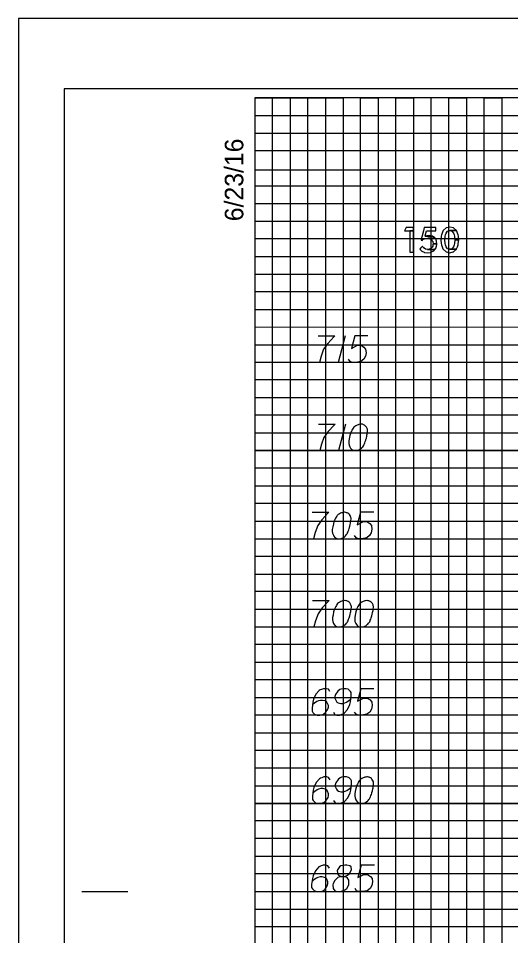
# Model space of a CAD drawing. Extents: x -13 to 323, y -5 to 1431.
# Drawn here: x -13.4 to 14.5, y 162.5 to 214.5 of the extents above; entities that cross this region are included whole.
import ezdxf

# ---------------------------------------------------------------- set-up
doc = ezdxf.new("R2010")
doc.units = 0
for name, color, linetype in [('Prop XS Elevation Labels', 7, 'Continuous'), ('Prop XS Offset Labels', 7, 'Continuous'), ('Sheet Cross Section CELL', 7, 'Continuous'), ('Sheet Cross Section Grid Major CELL', 7, 'Continuous'), ('Sheet Cross Section Grid Middle CELL', 7, 'Continuous'), ('Sheet Cross Section Grid Minor 1 CELL', 7, 'Continuous'), ('Sheet Cross Section Grid Minor 2 CELL', 7, 'Continuous'), ('Sheet Cutting Line CELL', 7, 'Continuous'), ('Sheet DOT Grid CELL', 7, 'Continuous'), ('Sheet Plot Border Inside CELL', 7, 'Continuous'), ('Sheet Plot Border Outside CELL', 7, 'Continuous')]:
    doc.layers.add(name, color=color, linetype=linetype)

msp = doc.modelspace()

# ---------------------------------------------------------------- linework, layer by layer
at = {"layer": 'Prop XS Elevation Labels'}
for p, q in [((5.124, 196.5), (4.723, 195)), ((5.142, 191.5), (4.74, 190))]:
    msp.add_line(p, q, dxfattribs=at)
for points in [[(3.589, 196.5), (4.533, 196.5), (4.474, 196.441), (4.132, 196.075), (3.896, 195.744), (3.754, 195.354), (3.659, 195)], [(6.411, 196.5), (5.667, 196.5), (5.478, 195.791), (5.821, 195.969), (6.022, 195.969), (6.187, 195.862), (6.282, 195.744), (6.305, 195.543), (6.27, 195.342), (6.175, 195.177), (6.01, 195.047), (5.726, 195), (5.514, 195), (5.408, 195.047), (5.313, 195.177)], [(3.606, 191.5), (4.551, 191.5), (4.492, 191.441), (4.149, 191.075), (3.913, 190.744), (3.772, 190.354), (3.677, 190)], [(6.039, 191.5), (6.016, 191.5), (5.945, 191.488), (5.898, 191.476), (5.862, 191.465), (5.803, 191.441), (5.732, 191.406), (5.673, 191.37), (5.614, 191.323), (5.579, 191.276), (5.543, 191.217), (5.508, 191.158), (5.472, 191.087), (5.449, 191.039), (5.425, 190.969), (5.39, 190.85), (5.354, 190.673), (5.331, 190.531), (5.331, 190.402), (5.343, 190.307), (5.39, 190.201), (5.425, 190.142), (5.484, 190.071), (5.555, 190.024), (5.591, 190.012), (5.661, 190), (5.72, 190), (5.815, 190.012), (5.898, 190.035), (5.957, 190.071), (6.039, 190.13), (6.075, 190.165), (6.122, 190.213), (6.157, 190.26), (6.181, 190.295), (6.205, 190.354), (6.217, 190.378), (6.24, 190.437), (6.264, 190.508), (6.287, 190.579), (6.299, 190.626), (6.311, 190.661), (6.323, 190.709), (6.347, 190.815), (6.358, 190.874), (6.37, 190.933), (6.382, 191.016), (6.394, 191.122), (6.394, 191.158), (6.382, 191.205), (6.37, 191.252), (6.335, 191.323), (6.299, 191.37), (6.264, 191.406), (6.217, 191.441), (6.169, 191.465), (6.134, 191.476), (6.098, 191.488), (6.039, 191.5)], [(3.258, 186.5), (4.203, 186.5), (4.144, 186.441), (3.801, 186.075), (3.565, 185.744), (3.423, 185.354), (3.329, 185)], [(5.1, 186.5), (5.077, 186.5), (5.006, 186.488), (4.959, 186.476), (4.923, 186.465), (4.864, 186.441), (4.793, 186.406), (4.734, 186.37), (4.675, 186.323), (4.64, 186.276), (4.604, 186.217), (4.569, 186.158), (4.534, 186.087), (4.51, 186.039), (4.486, 185.969), (4.451, 185.85), (4.415, 185.673), (4.392, 185.531), (4.392, 185.402), (4.404, 185.307), (4.451, 185.201), (4.486, 185.142), (4.545, 185.071), (4.616, 185.024), (4.652, 185.012), (4.723, 185), (4.781, 185), (4.876, 185.012), (4.959, 185.035), (5.018, 185.071), (5.1, 185.13), (5.136, 185.165), (5.183, 185.213), (5.219, 185.26), (5.242, 185.295), (5.266, 185.354), (5.278, 185.378), (5.301, 185.437), (5.325, 185.508), (5.349, 185.579), (5.36, 185.626), (5.372, 185.661), (5.384, 185.709), (5.408, 185.815), (5.419, 185.874), (5.431, 185.933), (5.443, 186.016), (5.455, 186.122), (5.455, 186.158), (5.443, 186.205), (5.431, 186.252), (5.396, 186.323), (5.36, 186.37), (5.325, 186.406), (5.278, 186.441), (5.23, 186.465), (5.195, 186.476), (5.16, 186.488), (5.1, 186.5)], [(6.742, 186.5), (5.998, 186.5), (5.809, 185.791), (6.152, 185.969), (6.352, 185.969), (6.518, 185.862), (6.612, 185.744), (6.636, 185.543), (6.6, 185.342), (6.506, 185.177), (6.341, 185.047), (6.057, 185), (5.845, 185), (5.738, 185.047), (5.644, 185.177)], [(3.276, 181.5), (4.22, 181.5), (4.161, 181.441), (3.819, 181.075), (3.583, 180.744), (3.441, 180.354), (3.346, 180)], [(5.118, 181.5), (5.094, 181.5), (5.024, 181.488), (4.977, 181.476), (4.941, 181.465), (4.882, 181.441), (4.811, 181.406), (4.752, 181.37), (4.693, 181.323), (4.658, 181.276), (4.622, 181.217), (4.587, 181.158), (4.551, 181.087), (4.528, 181.039), (4.504, 180.969), (4.469, 180.85), (4.433, 180.673), (4.409, 180.531), (4.409, 180.402), (4.421, 180.307), (4.469, 180.201), (4.504, 180.142), (4.563, 180.071), (4.634, 180.024), (4.669, 180.012), (4.74, 180), (4.799, 180), (4.894, 180.012), (4.977, 180.035), (5.036, 180.071), (5.118, 180.13), (5.154, 180.165), (5.201, 180.213), (5.236, 180.26), (5.26, 180.295), (5.283, 180.354), (5.295, 180.378), (5.319, 180.437), (5.342, 180.508), (5.366, 180.579), (5.378, 180.626), (5.39, 180.661), (5.402, 180.709), (5.425, 180.815), (5.437, 180.874), (5.449, 180.933), (5.461, 181.016), (5.473, 181.122), (5.473, 181.158), (5.461, 181.205), (5.449, 181.252), (5.413, 181.323), (5.378, 181.37), (5.342, 181.406), (5.295, 181.441), (5.248, 181.465), (5.213, 181.476), (5.177, 181.488), (5.118, 181.5)], [(6.37, 181.5), (6.346, 181.5), (6.276, 181.488), (6.228, 181.476), (6.193, 181.465), (6.134, 181.441), (6.063, 181.406), (6.004, 181.37), (5.945, 181.323), (5.909, 181.276), (5.874, 181.217), (5.838, 181.158), (5.803, 181.087), (5.779, 181.039), (5.756, 180.969), (5.721, 180.85), (5.685, 180.673), (5.661, 180.531), (5.661, 180.402), (5.673, 180.307), (5.721, 180.201), (5.756, 180.142), (5.815, 180.071), (5.886, 180.024), (5.921, 180.012), (5.992, 180), (6.051, 180), (6.146, 180.012), (6.228, 180.035), (6.287, 180.071), (6.37, 180.13), (6.406, 180.165), (6.453, 180.213), (6.488, 180.26), (6.512, 180.295), (6.535, 180.354), (6.547, 180.378), (6.571, 180.437), (6.594, 180.508), (6.618, 180.579), (6.63, 180.626), (6.642, 180.661), (6.653, 180.709), (6.677, 180.815), (6.689, 180.874), (6.701, 180.933), (6.713, 181.016), (6.724, 181.122), (6.724, 181.158), (6.713, 181.205), (6.701, 181.252), (6.665, 181.323), (6.63, 181.37), (6.594, 181.406), (6.547, 181.441), (6.5, 181.465), (6.464, 181.476), (6.429, 181.488), (6.37, 181.5)], [(4.262, 176.335), (4.168, 176.465), (4.061, 176.5), (3.896, 176.5), (3.778, 176.453), (3.707, 176.429), (3.648, 176.394), (3.459, 176.181), (3.329, 175.898), (3.294, 175.744), (3.246, 175.402), (3.246, 175.224), (3.294, 175.154), (3.388, 175.059), (3.423, 175.035), (3.542, 175), (3.695, 175), (3.813, 175.024), (3.896, 175.047), (4.014, 175.142), (4.132, 175.331), (4.168, 175.449), (4.168, 175.543), (4.109, 175.697), (4.061, 175.756), (3.979, 175.803), (3.837, 175.839), (3.73, 175.839), (3.601, 175.803), (3.518, 175.768), (3.376, 175.673), (3.305, 175.614), (3.27, 175.579)], [(4.451, 175.165), (4.545, 175.035), (4.652, 175), (4.817, 175), (4.935, 175.047), (5.006, 175.071), (5.065, 175.106), (5.254, 175.319), (5.384, 175.602), (5.419, 175.756), (5.467, 176.098), (5.467, 176.276), (5.419, 176.346), (5.325, 176.441), (5.289, 176.465), (5.171, 176.5), (5.018, 176.5), (4.9, 176.476), (4.817, 176.453), (4.699, 176.358), (4.581, 176.169), (4.545, 176.051), (4.545, 175.957), (4.604, 175.803), (4.652, 175.744), (4.734, 175.697), (4.876, 175.661), (4.982, 175.661), (5.112, 175.697), (5.195, 175.732), (5.337, 175.827), (5.408, 175.886), (5.443, 175.921)], [(6.754, 176.5), (6.01, 176.5), (5.821, 175.791), (6.163, 175.969), (6.364, 175.969), (6.529, 175.862), (6.624, 175.744), (6.647, 175.543), (6.612, 175.342), (6.517, 175.177), (6.352, 175.047), (6.069, 175), (5.856, 175), (5.75, 175.047), (5.655, 175.177)], [(4.28, 171.335), (4.185, 171.465), (4.079, 171.5), (3.914, 171.5), (3.795, 171.453), (3.725, 171.429), (3.666, 171.394), (3.477, 171.181), (3.347, 170.898), (3.311, 170.744), (3.264, 170.402), (3.264, 170.224), (3.311, 170.154), (3.406, 170.059), (3.441, 170.035), (3.559, 170), (3.713, 170), (3.831, 170.024), (3.914, 170.047), (4.032, 170.142), (4.15, 170.331), (4.185, 170.449), (4.185, 170.543), (4.126, 170.697), (4.079, 170.756), (3.996, 170.803), (3.854, 170.839), (3.748, 170.839), (3.618, 170.803), (3.536, 170.768), (3.394, 170.673), (3.323, 170.614), (3.288, 170.579)], [(4.468, 170.165), (4.563, 170.035), (4.669, 170), (4.835, 170), (4.953, 170.047), (5.024, 170.071), (5.083, 170.106), (5.272, 170.319), (5.401, 170.602), (5.437, 170.756), (5.484, 171.098), (5.484, 171.276), (5.437, 171.346), (5.342, 171.441), (5.307, 171.465), (5.189, 171.5), (5.036, 171.5), (4.917, 171.476), (4.835, 171.453), (4.717, 171.358), (4.598, 171.169), (4.563, 171.051), (4.563, 170.957), (4.622, 170.803), (4.669, 170.744), (4.752, 170.697), (4.894, 170.661), (5, 170.661), (5.13, 170.697), (5.213, 170.732), (5.354, 170.827), (5.425, 170.886), (5.461, 170.921)], [(6.382, 171.5), (6.358, 171.5), (6.287, 171.488), (6.24, 171.476), (6.204, 171.465), (6.145, 171.441), (6.074, 171.406), (6.015, 171.37), (5.956, 171.323), (5.921, 171.276), (5.885, 171.217), (5.85, 171.158), (5.815, 171.087), (5.791, 171.039), (5.767, 170.969), (5.732, 170.85), (5.697, 170.673), (5.673, 170.531), (5.673, 170.402), (5.685, 170.307), (5.732, 170.201), (5.767, 170.142), (5.827, 170.071), (5.897, 170.024), (5.933, 170.012), (6.004, 170), (6.063, 170), (6.157, 170.012), (6.24, 170.035), (6.299, 170.071), (6.382, 170.13), (6.417, 170.165), (6.464, 170.213), (6.5, 170.26), (6.523, 170.295), (6.547, 170.354), (6.559, 170.378), (6.582, 170.437), (6.606, 170.508), (6.63, 170.579), (6.642, 170.626), (6.653, 170.661), (6.665, 170.709), (6.689, 170.815), (6.701, 170.874), (6.712, 170.933), (6.724, 171.016), (6.736, 171.122), (6.736, 171.158), (6.724, 171.205), (6.712, 171.252), (6.677, 171.323), (6.642, 171.37), (6.606, 171.406), (6.559, 171.441), (6.512, 171.465), (6.476, 171.476), (6.441, 171.488), (6.382, 171.5)], [(4.238, 166.335), (4.144, 166.465), (4.038, 166.5), (3.872, 166.5), (3.754, 166.453), (3.683, 166.429), (3.624, 166.394), (3.435, 166.181), (3.305, 165.898), (3.27, 165.744), (3.223, 165.402), (3.223, 165.224), (3.27, 165.154), (3.364, 165.059), (3.4, 165.035), (3.518, 165), (3.671, 165), (3.79, 165.024), (3.872, 165.047), (3.99, 165.142), (4.108, 165.331), (4.144, 165.449), (4.144, 165.543), (4.085, 165.697), (4.038, 165.756), (3.955, 165.803), (3.813, 165.839), (3.707, 165.839), (3.577, 165.803), (3.494, 165.768), (3.352, 165.673), (3.282, 165.614), (3.246, 165.579)], [(4.899, 165.85), (5.065, 165.85), (5.112, 165.862), (5.254, 165.921), (5.36, 166.016), (5.478, 166.24), (5.466, 166.406), (5.384, 166.465), (5.218, 166.5), (5.1, 166.5), (4.876, 166.465), (4.805, 166.406), (4.687, 166.228), (4.675, 166.169), (4.699, 165.992), (4.746, 165.921), (4.899, 165.85), (4.711, 165.803), (4.533, 165.626), (4.439, 165.449), (4.427, 165.39), (4.439, 165.165), (4.545, 165.047), (4.687, 165), (4.829, 165), (5.053, 165.059), (5.218, 165.165), (5.325, 165.378), (5.337, 165.449), (5.325, 165.638), (5.23, 165.803), (5.065, 165.85)], [(6.777, 166.5), (6.033, 166.5), (5.844, 165.791), (6.187, 165.969), (6.388, 165.969), (6.553, 165.862), (6.648, 165.744), (6.671, 165.543), (6.636, 165.342), (6.541, 165.177), (6.376, 165.047), (6.092, 165), (5.88, 165), (5.773, 165.047), (5.679, 165.177)]]:
    msp.add_lwpolyline(points, dxfattribs=at)
at = {"layer": 'Prop XS Offset Labels'}
for points in [[(8.581, 202.641), (8.492, 202.459), (8.99, 202.459), (8.99, 202.641)], [(8.781, 202.459), (8.781, 201.25), (8.99, 201.25), (8.99, 202.459)], [(9.427, 201.94), (9.424, 201.928), (9.495, 201.928), (9.508, 201.94), (9.524, 201.954), (9.595, 201.997), (9.627, 202.007), (9.697, 202.029), (9.811, 202.035), (10.219, 202.035), (10.211, 202.05), (10.076, 202.145), (9.655, 202.145), (9.658, 202.158), (9.658, 202.158), (9.663, 202.178), (9.738, 202.456), (10.263, 202.456), (10.263, 202.641), (9.6, 202.641), (9.554, 202.456), (9.486, 202.178), (9.481, 202.158), (9.478, 202.145), (9.454, 202.05), (9.451, 202.035), (9.449, 202.029), (9.444, 202.007), (9.441, 201.997), (9.431, 201.954)], [(10.851, 201.255), (11.051, 201.214), (11.245, 201.255), (11.256, 201.257), (11.422, 201.409), (11.047, 201.409), (11.038, 201.411), (11.033, 201.413), (10.928, 201.442), (10.841, 201.555), (10.841, 201.556), (10.841, 201.556), (10.813, 201.657), (10.813, 201.659), (10.793, 201.732), (10.792, 201.736), (10.774, 201.939), (10.774, 201.941), (10.774, 201.943), (10.792, 202.145), (10.812, 202.222), (10.813, 202.224), (10.839, 202.322), (10.84, 202.325), (10.928, 202.44), (11.041, 202.469), (11.045, 202.47), (11.055, 202.473), (11.425, 202.473), (11.262, 202.622), (11.254, 202.624), (11.053, 202.668), (11.053, 202.668), (10.845, 202.624), (10.843, 202.622), (10.681, 202.473), (10.678, 202.47), (10.678, 202.469), (10.665, 202.44), (10.618, 202.325), (10.617, 202.322), (10.577, 202.224), (10.576, 202.222), (10.568, 202.145), (10.547, 201.943), (10.547, 201.941), (10.547, 201.939), (10.567, 201.736), (10.568, 201.732), (10.575, 201.659), (10.575, 201.657), (10.616, 201.556), (10.617, 201.555), (10.663, 201.442), (10.675, 201.413), (10.676, 201.411), (10.679, 201.409), (10.848, 201.257)], [(11.312, 202.145), (11.328, 201.943), (11.555, 201.943), (11.536, 202.145), (11.528, 202.222), (11.527, 202.224), (11.527, 202.224), (11.488, 202.322), (11.488, 202.322), (11.487, 202.325), (11.441, 202.44), (11.44, 202.44), (11.429, 202.469), (11.428, 202.47), (11.425, 202.473), (11.055, 202.473), (11.065, 202.47), (11.068, 202.469), (11.175, 202.44), (11.262, 202.325), (11.265, 202.322), (11.291, 202.224), (11.291, 202.222)], [(9.424, 201.928), (9.482, 201.916), (9.495, 201.928)], [(9.692, 202.158), (9.655, 202.145), (10.076, 202.145), (10.058, 202.158), (9.961, 202.178), (9.75, 202.178)], [(9.888, 202.192), (9.75, 202.178), (9.96, 202.178), (9.888, 202.192)], [(10.083, 201.841), (10.105, 201.721), (10.318, 201.721), (10.307, 201.841), (10.307, 201.841), (10.303, 201.881), (10.284, 201.916), (10.278, 201.928), (10.271, 201.94), (10.263, 201.954), (10.24, 201.997), (10.235, 202.007), (10.223, 202.029), (10.219, 202.035), (9.811, 202.035), (9.838, 202.029), (9.928, 202.007), (9.943, 201.997), (10.003, 201.954), (10.024, 201.94), (10.031, 201.928), (10.038, 201.916), (10.059, 201.881)], [(11.058, 201.411), (11.047, 201.409), (11.422, 201.409), (11.425, 201.411), (11.426, 201.413), (11.438, 201.442), (11.485, 201.555), (11.485, 201.556), (11.527, 201.657), (11.528, 201.659), (11.535, 201.732), (11.535, 201.736), (11.555, 201.939), (11.556, 201.941), (11.555, 201.943), (11.328, 201.943), (11.328, 201.941), (11.328, 201.939), (11.312, 201.736), (11.312, 201.732), (11.292, 201.659), (11.291, 201.657), (11.264, 201.556), (11.263, 201.555), (11.175, 201.442), (11.063, 201.413)], [(9.626, 201.233), (9.762, 201.214), (9.959, 201.233), (9.968, 201.237), (10.091, 201.297), (10.091, 201.297), (10.141, 201.321), (10.185, 201.375), (10.204, 201.399), (9.793, 201.399), (9.683, 201.418), (9.682, 201.419), (9.679, 201.42), (9.596, 201.466), (9.586, 201.477), (9.58, 201.483), (9.58, 201.483), (9.529, 201.535), (9.497, 201.585), (9.497, 201.585), (9.451, 201.535), (9.404, 201.483), (9.399, 201.477), (9.39, 201.466), (9.348, 201.42), (9.347, 201.419), (9.348, 201.418), (9.363, 201.399), (9.382, 201.375), (9.445, 201.321), (9.474, 201.297), (9.598, 201.237)], [(9.9, 201.418), (9.793, 201.399), (10.204, 201.399), (10.22, 201.418), (10.221, 201.419), (10.222, 201.42), (10.222, 201.42), (10.259, 201.466), (10.268, 201.477), (10.27, 201.483), (10.284, 201.535), (10.299, 201.59), (10.322, 201.674), (10.318, 201.721), (10.105, 201.721), (10.097, 201.674), (10.082, 201.59), (10.047, 201.535), (10.014, 201.483), (10.004, 201.477), (9.987, 201.466), (9.913, 201.42), (9.905, 201.419)]]:
    msp.add_lwpolyline(points, close=True, dxfattribs=at)
at = {"layer": 'Sheet Cross Section CELL'}
for p, q in [((-9.8, 165), (-7.3, 165)), ((-9.7, 165), (-7.2, 165))]:
    msp.add_line(p, q, dxfattribs=at)
msp.add_lwpolyline([(320, 210), (0, 210), (0, 0), (320, 0)], close=True, dxfattribs=at)
at = {"layer": 'Sheet Cross Section Grid Major CELL'}
for p, q in [((10, 210), (0, 210)), ((10, 0), (10, 210))]:
    msp.add_line(p, q, dxfattribs=at)
for points in [[(0, 200), (320, 200), (320, 190), (0, 190)], [(0, 180), (320, 180), (320, 170), (0, 170)]]:
    msp.add_lwpolyline(points, dxfattribs=at)
at = {"layer": 'Sheet Cross Section Grid Middle CELL'}
for points in [[(0, 210), (5, 210), (5, 0)], [(0, 205), (275, 205)], [(0, 185), (320, 185), (320, 195), (0, 195)], [(0, 165), (320, 165), (320, 175), (0, 175)]]:
    msp.add_lwpolyline(points, dxfattribs=at)
at = {"layer": 'Sheet Cross Section Grid Minor 1 CELL'}
for p, q in [((0, 209), (260, 209)), ((260, 207.98), (0, 207.98)), ((0, 207.98), (0, 207)), ((0, 207), (260, 207)), ((260, 205.89), (0, 205.89)), ((0, 205.89), (0, 204)), ((0, 204), (320, 204))]:
    msp.add_line(p, q, dxfattribs=at)
for points in [[(0, 203), (270, 203), (320, 203), (320, 202), (0, 202)], [(0, 201), (320, 201), (320, 199), (0, 199)], [(0, 198), (320, 198), (320, 197), (0, 196.98)], [(0, 196), (320, 196), (320, 194), (0, 194)], [(0, 193), (320, 193), (320, 192), (0, 192)], [(0, 191), (320, 191), (320, 189), (0, 189)], [(0, 188), (320, 188), (320, 187), (0, 187)], [(0, 186), (320, 186), (320, 184), (0, 184)], [(0, 183), (320, 183), (320, 182), (0, 182)], [(0, 181), (320, 181), (320, 179), (0, 179)], [(0, 178), (320, 178), (320, 177), (0, 177)], [(0, 176), (320, 176), (320, 173.95), (320, 173), (320, 172), (0, 172)], [(0, 174), (320, 174), (320, 173), (0, 173)], [(0, 171), (320, 171), (320, 169), (0, 169.03)], [(0, 169.03), (320, 169), (320, 168), (0, 168)], [(0, 167), (320, 167), (320, 166), (0, 166)], [(0, 164), (320, 164), (320, 163), (0, 163)]]:
    msp.add_lwpolyline(points, dxfattribs=at)
at = {"layer": 'Sheet Cross Section Grid Minor 2 CELL'}
for points in [[(0, 0), (1, 0), (1, 210), (2, 210), (2, 0)], [(2, 0), (3, 0), (3, 210), (4, 210), (4, 0)], [(5, 0), (6, 0), (6, 210), (7, 210), (7, 0)], [(7, 0), (8, 0), (8, 210), (9, 210), (9, 0)], [(10, 0), (11, 0), (11, 210), (12, 210), (12, 0)], [(12, 0), (13, 0), (13, 210), (14, 210), (14, 0)]]:
    msp.add_lwpolyline(points, dxfattribs=at)
at = {"layer": 'Sheet Cutting Line CELL'}
for p, q in [((323.3, 214.5), (-13.4, 214.5)), ((-13.4, 214.5), (-13.4, -4.5))]:
    msp.add_line(p, q, dxfattribs=at)
at = {"layer": 'Sheet DOT Grid CELL'}
for p, q in [((10, 0), (10, 210)), ((0, 200), (320, 200)), ((0, 190), (320, 190)), ((0, 180), (320, 180)), ((0, 170), (320, 170))]:
    msp.add_line(p, q, dxfattribs=at)
at = {"layer": 'Sheet Plot Border Inside CELL'}
msp.add_lwpolyline([(-10.8, -0.5), (322.4, -0.5), (322.4, 210.5), (-10.8, 210.5)], close=True, dxfattribs=at)
at = {"layer": 'Sheet Plot Border Outside CELL'}
msp.add_lwpolyline([(-13.4, -4.5), (323.3, -4.5), (323.3, 214.5), (-13.4, 214.5)], close=True, dxfattribs=at)

# ---------------------------------------------------------------- texts
at = {"layer": 'Sheet Cross Section CELL'}
msp.add_text('6/23/16', height=1.05, rotation=90, dxfattribs=at).set_placement((-0.65, 203))

doc.saveas('drawing.dxf')
